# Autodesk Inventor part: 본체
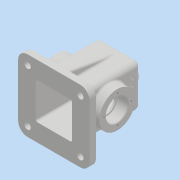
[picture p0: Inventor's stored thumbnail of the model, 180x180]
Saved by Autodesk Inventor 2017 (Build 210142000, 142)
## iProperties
Part Number: 본체
Material: 일반
Document SubType Name: Modeling
Designer: MRC
Density: 1 g/cm^3
Appearance: 기본값
Author: MRC
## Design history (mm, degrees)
sketch "스케치1"
  geometry: L1 (-34, 34)-(34, 34); L2 (34, 34)-(34, -34); L3 (34, -34)-(-34, -34); L4 (-34, -34)-(-34, 34); L5 (-34, 34)-(34, -34); L6 (34, 34)-(-34, -34); 1 further point
  constraints: 12 end point, 2 midpoint, 2 parallel, 1 horizontal, 1 perpendicular
  dimensions: "d0" = 68 distance of L2.end L3.end; "d1" = 68 distance of L1.end L2.end
extrude "돌출1" new body sketch "스케치1" distance "d2" = 53; taper "d4" = 0 deg; dims "d3" = 52, "d5" = 0
fillet "모깎기1" dims "d6" = 8
fillet "모깎기2" dims "d7" = 8
feature "쉘1" dims "d8" = 5
node "작업 평면1"
sketch "스케치3"
  geometry: C1 r 28.5 at (0, 0); 1 further point
  constraints: 1 centre point, 1 coincident
  dimensions: "d11" = 57 diameter of C1
extrude "돌출2" join sketch "스케치3" stored distance "d12" = 53; taper "d13" = 0 deg
fillet "모깎기3" dims "d14" = 3
hole "구멍1" diameter "d17" = 30; stored, may be unused: countersink angle "d21" = 90 deg, drill point angle "d23" = 118 deg; dims "d15" = 10, "d16" = 10, "d18" = 6, "d19" = 35, "d20" = 17, "d22" = 8
sketch "스케치4"
  geometry: C1 r 17.5 at (0, 0) reference; 1 further point
  constraints: 1 vertical alignment
  dimensions: "d24" = 22 distance of C1.centre point (0, 22)
hole "구멍2" sketch "스케치4" at (0, 22) diameter "d25" = 3.242; stored, may be unused: countersink angle "d29" = 90 deg, drill point angle "d31" = 118 deg; dims "d26" = 8, "d27" = 35, "d28" = 17, "d30" = 10
chamfer "모따기1" distance "d35" = 1; stored, may be unused: second distance "d36" = 2, angle "d37" = 45 deg
fillet "모깎기4" dims "d38" = 0.3
fillet "모깎기5" dims "d39" = 3
sketch "스케치5"
  geometry: C1 r 20 at (0, 0); 1 further point
  constraints: 1 centre point, 1 coincident
  dimensions: "d40" = 40 diameter of C1
extrude "돌출3" join sketch "스케치5" distance "d41" = 10; taper "d42" = 0 deg
feature "면 기울기1" dims angle "d43" = 8 deg
hole "구멍3" diameter "d46" = 22.835; stored, may be unused: countersink angle "d50" = 90 deg, drill point angle "d52" = 118 deg; dims "d44" = 10, "d45" = 10, "d47" = 50, "d48" = 35, "d49" = 17, "d51" = 59.3
sketch "스케치6"
  geometry: L1 (-26, -34)-(26, -34) reference; L2 (34, -26)-(34, 26) reference; L3 (26, 34)-(-26, 34) reference; L4 (-34, 26)-(-34, -26) reference; L5 (-57, 57)-(57, 57); L6 (57, 57)-(57, -57); L7 (57, -57)-(-57, -57); L8 (-57, -57)-(-57, 57); L9 (-57, 57)-(57, -57); L10 (57, 57)-(-57, -57); A1 r 8 centre (-26, -26) between (-34, -26) and (-26, -34) reference; A2 r 8 centre (26, -26) between (26, -34) and (34, -26) reference; A3 r 8 centre (26, 26) between (34, 26) and (26, 34) reference; A4 r 8 centre (-26, 26) between (-26, 34) and (-34, 26) reference; 1 further point
  constraints: 12 end point, 2 midpoint, 2 parallel, 1 horizontal, 1 perpendicular
  dimensions: "d53" = 114 distance of L6.end L7.end; "d54" = 114 distance of L5.end L6.end
extrude "돌출4" join sketch "스케치6" distance "d55" = 10; taper "d56" = 0 deg
fillet "모깎기6" dims "d57" = 15
sketch "스케치7"
  geometry: A1 r 15 centre (-42, -42) between (-57, -42) and (-42, -57) reference; A2 r 15 centre (42, -42) between (42, -57) and (57, -42) reference; A3 r 15 centre (42, 42) between (57, 42) and (42, 57) reference; A4 r 15 centre (-42, 42) between (-42, 57) and (-57, 42) reference; 5 further points
  constraints: 4 coincident
hole "구멍4" sketch "스케치7" at (42, -42), (-42, -42), (-42, 42), (42, 42) diameter "d58" = 10; stored, may be unused: countersink angle "d62" = 90 deg, drill point angle "d64" = 118 deg; dims "d59" = 50, "d60" = 18, "d61" = 2, "d63" = 59.3
sketch "스케치8"
  geometry: L1 (-42, 49)-(-27.378, 46.422); L2 (-42, 51)-(-42, 33) reference; L3 (-42, 57)-(-52, 57) reference; 1 further point
  constraints: 2 end point, 1 point on line
  dimensions: "d65" = 8 distance from line of L1.start L3; "d66" = 10 deg angle of L1 L3
feature "리브1" sketch "스케치8" dims "d67" = 1, "d68" = 10, "d69" = 0, "d70" = 0, "d71" = 1, "d72" = 1
fillet "모깎기7" dims "d73" = 3
fillet "모깎기8" dims "d74" = 3
fillet "모깎기9" dims "d75" = 3
fillet "모깎기10" dims "d76" = 3
fillet "모깎기11" dims "d77" = 3
sketch "스케치9"
  geometry: L1 (-8, 0)-(-8, -84) reference; L2 (46, 18)-(6, 18) reference; 1 further point
  constraints: 1 other
  dimensions: "d78" = 34 distance from line of point (26, -7) L1; "d79" = 25 distance from line of point (26, -7) L2
feature "엠보싱1" sketch "스케치9" dims "d0" = 68, "d1" = 68, "d80" = 0.5, "d81" = 0
node "솔리드1"
pattern_circular "원형 패턴1" dims angle "d33" = 360 deg
mirror "미러1"
mirror "미러2"
other parameters: "d10" = 49
